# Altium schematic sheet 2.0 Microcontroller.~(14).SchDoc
size A4; SheetNumber: 2; SheetTotal: 7
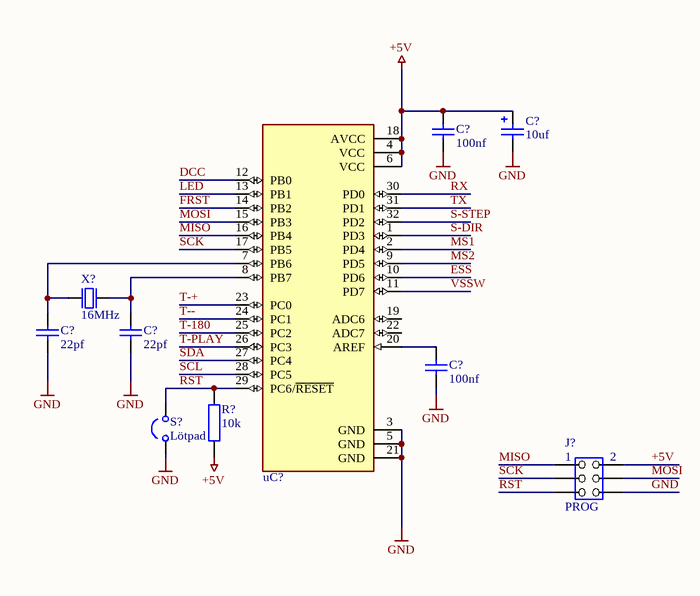
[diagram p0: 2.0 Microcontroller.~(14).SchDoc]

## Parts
(Parts that share a designator on the sheet are numbered #1, #2 ... from top to bottom, then left to right.)
C?#1  10uf  [C_SMD_D-TYP]
C?#2  100nf  [C_SMD_0805]
C?#3  22pf  [C_SMD_0805]
C?#4  22pf  [C_SMD_0805]
C?#5  100nf  [C_SMD_0805]
J?  PROG  [J_2x3]
R?  10k  [R_SMD_0805]
S?  Lötpad  [S_SMD_Pad-NO]
uC?  ATMega328(p)-AU  [TQFP-32]  (value not drawn)
X?  16MHz  [X_SMD_XTAL]

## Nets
+5V: C?#1.1 C?#2.1 J?.2 R?.1 uC?.4(VCC) uC?.6(VCC) uC?.18(AVCC)
GND: C?#1.2 C?#2.2 C?#3.2 C?#4.2 C?#5.2 J?.6 S?.1 uC?.3(GND) uC?.5(GND) uC?.21(GND)
DCC: uC?.12(PB0)
ESS: uC?.10(PD6)
FRST: uC?.14(PB2)
LED: uC?.13(PB1)
MISO: J?.1 uC?.16(PB4)
MOSI: J?.4 uC?.15(PB3)
MS1: uC?.2(PD4)
MS2: uC?.9(PD5)
RST: J?.5 R?.2 S?.2 uC?.29(PC6/~{RESET})
RX: uC?.30(PD0)
S-DIR: uC?.1(PD3)
S-STEP: uC?.32(PD2)
SCK: J?.3 uC?.17(PB5)
SCL: uC?.28(PC5)
SDA: uC?.27(PC4)
T-180: uC?.25(PC2)
T-+: uC?.23(PC0)
T--: uC?.24(PC1)
T-PLAY: uC?.26(PC3)
TX: uC?.31(PD1)
VSSW: uC?.11(PD7)
NetC?#3_1: C?#3.1 uC?.7(PB6) X?.1
NetC?#4_1: C?#4.1 uC?.8(PB7) X?.2
NetC?#5_1: C?#5.1 uC?.20(AREF)

Not connected (* = marked no-connect by the designer): uC? 19(ADC6) 22(ADC7)

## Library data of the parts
C?#1 = C_SMD_ELK: SMD Elektrolytkondensator
C?#2-C?#5 = C_SMD_KO: Kondensator SMD Universal, Keramik, Folie, usw.
J? = J_THT_IDC 2x3: Stecker
R? = R_SMD_Widerstand: Widerstand SMD
S? = S_SMD_Jumper: Lötverbinder
uC? = UC_ATMega328P-AU: Microcontroller
X? = X_SMD_Quarz: Quarz SMD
